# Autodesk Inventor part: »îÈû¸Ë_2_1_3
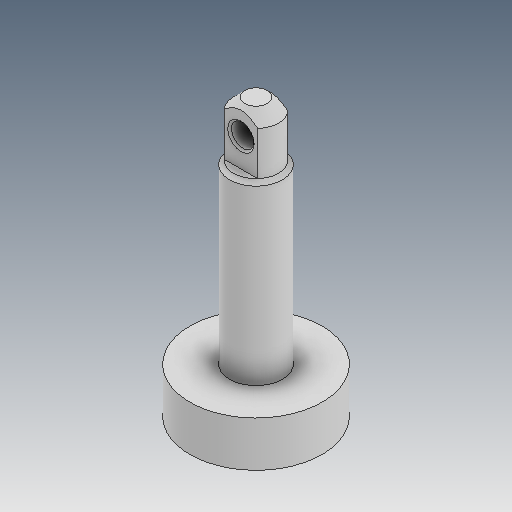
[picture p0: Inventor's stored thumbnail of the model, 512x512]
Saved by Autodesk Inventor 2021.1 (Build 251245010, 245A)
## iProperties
Created: 2019-04
Part Number: »îÈû¸Ë_2_1_3
Material: Ogólny
Document SubType Name: Modeling
Designer: user
Density: 1 g/cm^3
Appearance: Domyślna
Author: user
Revision Number: ÈÎºÎ
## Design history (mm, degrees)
feature "ÊäÈë1"
node "Bryła1"
